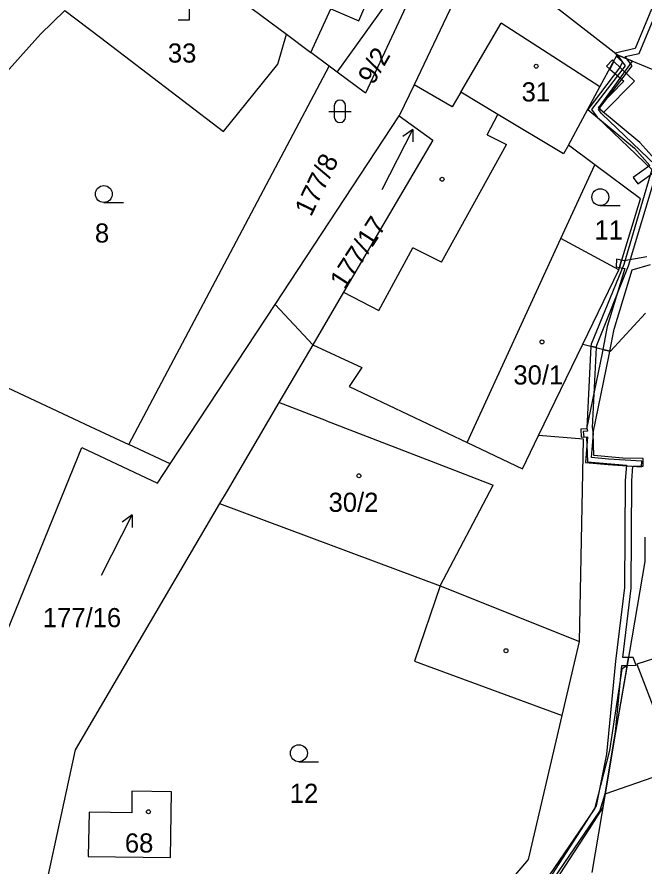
# Model space of a CAD drawing. Extents: x -779723 to -777378, y -1011169 to -1009297.
# Drawn here: x -779222.9 to -779167.2, y -1010377.1 to -1010301.7 of the extents above; entities that cross this region are included whole.
import ezdxf

# ---------------------------------------------------------------- set-up
doc = ezdxf.new("R2010")
doc.units = 0
for name, color, linetype in [('Hranice parcel', 7, 'Continuous'), ('Parcelní čísla', 7, 'Continuous'), ('Vnitřní kresba', 7, 'Continuous'), ('Věcná břemena k části', 7, 'Continuous'), ('Značky budov', 7, 'Continuous'), ('Značky kultur', 7, 'Continuous')]:
    doc.layers.add(name, color=color, linetype=linetype)

msp = doc.modelspace()

# ---------------------------------------------------------------- linework, layer by layer
at = {"layer": 'Hranice parcel'}
for p, q in [((-779198.99, -1010303.26), (-779196.83, -1010304.88)), ((-779195.2, -1010306.1), (-779196.83, -1010304.88)), ((-779212.98, -1010339.7), (-779195.2, -1010306.1)), ((-779194.49, -1010306.63), (-779195.2, -1010306.1)), ((-779187.65, -1010307.74), (-779188.97, -1010310.51)), ((-779200, -1010327.27), (-779188.97, -1010310.51)), ((-779171.61, -1010314.85), (-779173.96, -1010313.1)), ((-779172.68, -1010330.78), (-779169.49, -1010324.18)), ((-779209.31, -1010341.42), (-779200, -1010327.27)), ((-779196.66, -1010330.84), (-779200, -1010327.27)), ((-779176.6, -1010338.9), (-779172.68, -1010330.78)), ((-779209.31, -1010341.42), (-779212.98, -1010339.7)), ((-779170.69, -1010370.7), (-779171.88, -1010377.7))]:
    msp.add_line(p, q, dxfattribs=at)
for points in [[(-779196.83, -1010304.88), (-779195.06, -1010301.02), (-779192.55, -1010302.07), (-779188.41, -1010292.39), (-779193.1, -1010290.28), (-779191.55, -1010286.87)], [(-779194.49, -1010306.63), (-779190.18, -1010300.61), (-779185.64, -1010294.9)], [(-779185.64, -1010294.9), (-779191.98, -1010308.5), (-779194.49, -1010306.63)], [(-779209.36, -1010295.51), (-779204.33, -1010299.27), (-779198.99, -1010303.26)], [(-779181.85, -1010295.53), (-779183.92, -1010299.88), (-779187.65, -1010307.74)], [(-779169.61, -1010305.1), (-779177.81, -1010298.69), (-779179.01, -1010297.75), (-779181.85, -1010295.53)], [(-779241.34, -1010326.4), (-779229.64, -1010317.38), (-779225.92, -1010308.91), (-779220.82, -1010303.25), (-779218.66, -1010301.14)], [(-779218.66, -1010301.14), (-779215.5, -1010303.55), (-779204.57, -1010311.9), (-779199.75, -1010305.93), (-779198.99, -1010303.26)], [(-779173.96, -1010313.1), (-779171.15, -1010307.94), (-779169.61, -1010305.1)], [(-779169.61, -1010305.1), (-779160.99, -1010308.63), (-779155.46, -1010307.78), (-779148.16, -1010306.65)], [(-779173.96, -1010313.1), (-779174.39, -1010313.89), (-779180.21, -1010310.38), (-779183.51, -1010308.4), (-779184.27, -1010309.7), (-779187.65, -1010307.74)], [(-779188.97, -1010310.51), (-779186, -1010312.66), (-779190.73, -1010320.73), (-779193.92, -1010326.17), (-779196.66, -1010330.84)], [(-779169.49, -1010324.18), (-779174.62, -1010321.41), (-779171.61, -1010314.85)], [(-779169.49, -1010324.18), (-779167.55, -1010317.87), (-779171.61, -1010314.85)], [(-779241.34, -1010326.4), (-779216.41, -1010338.1), (-779212.98, -1010339.7)], [(-779172.68, -1010330.78), (-779170.22, -1010331.41), (-779167.12, -1010328.04)], [(-779196.66, -1010330.84), (-779199.66, -1010335.95), (-779204.25, -1010343.79), (-779204.93, -1010344.94)], [(-779196.66, -1010330.84), (-779192.3, -1010332.84), (-779193.43, -1010334.55), (-779182.94, -1010339.51), (-779178.02, -1010341.84), (-779176.6, -1010338.9)], [(-779174.51, -1010363.75), (-779172.96, -1010357.18), (-779172.6, -1010339.21), (-779176.6, -1010338.9)], [(-779237.61, -1010383.13), (-779227.1, -1010364.33), (-779217.17, -1010339.95), (-779210.43, -1010343.11), (-779209.31, -1010341.42)], [(-779204.93, -1010344.94), (-779217.76, -1010366.81), (-779222.02, -1010386.49)], [(-779204.93, -1010344.94), (-779185.33, -1010352.25), (-779187.61, -1010358.93), (-779174.51, -1010363.75)], [(-779167.16, -1010347.93), (-779167.17, -1010350.08), (-779168.77, -1010359.47), (-779169.76, -1010365.24), (-779170.69, -1010370.7)], [(-779170.69, -1010370.7), (-779164.31, -1010368.5), (-779150.92, -1010363.88), (-779148.14, -1010362.87)], [(-779181.94, -1010381.76), (-779177.51, -1010376.54), (-779174.51, -1010363.75)], [(-779212.73, -1010372.38), (-779216.52, -1010372.33), (-779216.59, -1010376.27), (-779209.28, -1010376.35), (-779209.21, -1010370.54), (-779212.71, -1010370.47), (-779212.73, -1010372.38)]]:
    msp.add_lwpolyline(points, dxfattribs=at)
at = {"layer": 'Vnitřní kresba'}
for p, q in [((-779183.51, -1010308.4), (-779179.93, -1010302.29)), ((-779171.15, -1010307.94), (-779179.93, -1010302.29)), ((-779181.18, -1010312.2), (-779180.21, -1010310.38)), ((-779181.18, -1010312.2), (-779179.44, -1010313.05)), ((-779185.22, -1010323.51), (-779179.44, -1010313.05)), ((-779182.94, -1010339.51), (-779174.62, -1010321.41)), ((-779190.79, -1010327.79), (-779187.78, -1010322.22)), ((-779185.22, -1010323.51), (-779187.78, -1010322.22)), ((-779193.92, -1010326.17), (-779190.79, -1010327.79)), ((-779195.44, -1010337.58), (-779199.66, -1010335.95)), ((-779195.44, -1010337.58), (-779184.06, -1010341.97)), ((-779184.06, -1010341.97), (-779180.63, -1010343.29)), ((-779185.33, -1010352.25), (-779180.63, -1010343.29)), ((-779185.33, -1010352.25), (-779172.96, -1010357.18)), ((-779152.93, -1010354.43), (-779167.87, -1010359.19)), ((-779167.87, -1010359.19), (-779166.01, -1010364.05))]:
    msp.add_line(p, q, dxfattribs=at)
at = {"layer": 'Věcná břemena k části'}
for points in [[(-779165.25, -1010299.1), (-779165.69, -1010298.88), (-779168.03, -1010304.53), (-779169.81, -1010304.95), (-779169.61, -1010305.1), (-779168.76, -1010305.45), (-779168.92, -1010305.23), (-779167.67, -1010304.97)], [(-779170.83, -1010310.2), (-779168.09, -1010307.42), (-779169.92, -1010305.67), (-779170.29, -1010306.35), (-779169.03, -1010307.44), (-779171.29, -1010309.74)], [(-779170.29, -1010306.35), (-779169.92, -1010305.67), (-779170.05, -1010305.54), (-779170.57, -1010306.1)], [(-779169.23, -1010323.33), (-779169.69, -1010323.24), (-779169.71, -1010323.91), (-779169.42, -1010323.97)], [(-779171.95, -1010330.97), (-779172.32, -1010338.23), (-779172.27, -1010338.5), (-779172.63, -1010338.54), (-779172.57, -1010339.04), (-779172.25, -1010339), (-779172.45, -1010341.3), (-779170.41, -1010341.47), (-779167.46, -1010341.66), (-779167.43, -1010341.17), (-779170.38, -1010340.98), (-779171.91, -1010340.84), (-779171.72, -1010338.7), (-779171.82, -1010338.19), (-779171.45, -1010331.09)], [(-779168.62, -1010358.6), (-779168.74, -1010359.3), (-779167.95, -1010359.28), (-779168.21, -1010358.59)], [(-779168.84, -1010359.9), (-779168.74, -1010359.3), (-779169.22, -1010359.65), (-779170.31, -1010366.86), (-779171.63, -1010372.03), (-779178.35, -1010381.89), (-779186.23, -1010391.51), (-779188.9, -1010390.68), (-779189.2, -1010391.07), (-779186.47, -1010391.96), (-779189.03, -1010399.39), (-779189.26, -1010403.35), (-779188.7, -1010402.34), (-779188.53, -1010399.49), (-779185.93, -1010391.92), (-779177.95, -1010382.19), (-779171.17, -1010372.23), (-779170.69, -1010370.7)]]:
    msp.add_lwpolyline(points, close=True, dxfattribs=at)
for points in [[(-779166.02, -1010314.64), (-779167.62, -1010312.88), (-779171.28, -1010309.83), (-779168.26, -1010305.65), (-779169.61, -1010305.1), (-779169.67, -1010305.21), (-779169.15, -1010305.75), (-779169.41, -1010306.24), (-779172.24, -1010309.93), (-779168.1, -1010313.38), (-779166.71, -1010314.91), (-779168.2, -1010315.98), (-779167.79, -1010316.55), (-779166.22, -1010315.42)], [(-779166.18, -1010314.93), (-779171.03, -1010310.31), (-779171.29, -1010309.95), (-779168.29, -1010306.08), (-779168.76, -1010305.45), (-779169.61, -1010305.1), (-779168.91, -1010306.08), (-779171.91, -1010309.93), (-779171.41, -1010310.63), (-779166.54, -1010315.27), (-779169.04, -1010323.72), (-779171.94, -1010330.78), (-779171.95, -1010330.97), (-779171.45, -1010331.09), (-779171.44, -1010330.86), (-779168.61, -1010323.84), (-779166.16, -1010315.66)], [(-779166.98, -1010323.02), (-779169.01, -1010323.38), (-779169.23, -1010323.33), (-779169.42, -1010323.97), (-779168.95, -1010324.06), (-779170.52, -1010329.22), (-779170.9, -1010331.24), (-779170.27, -1010331.4), (-779169.89, -1010329.45), (-779168.3, -1010324.18), (-779166.66, -1010323.72)], [(-779175.58, -1010379.18), (-779172.09, -1010373.8), (-779170.9, -1010371.95), (-779170.69, -1010370.7), (-779169.76, -1010365.24), (-779169.2, -1010359.31), (-779168.74, -1010359.3), (-779168.62, -1010358.6), (-779169.12, -1010358.61), (-779168.37, -1010352.44), (-779168.32, -1010342.91), (-779168.22, -1010341.61), (-779167.31, -1010341.62), (-779167.31, -1010340.92), (-779169.12, -1010340.9), (-779171.69, -1010340.67), (-779171.75, -1010338.65), (-779170.33, -1010331.72), (-779170.27, -1010331.4), (-779170.9, -1010331.24), (-779170.97, -1010331.59), (-779172.35, -1010338.31), (-779172.84, -1010338.33), (-779172.82, -1010339.03), (-779172.34, -1010339.01), (-779172.27, -1010341.23), (-779168.81, -1010341.53), (-779168.92, -1010342.89), (-779168.97, -1010352.4), (-779169.77, -1010358.94), (-779170.57, -1010367.18), (-779171.48, -1010371.76), (-779172.59, -1010373.48), (-779176.06, -1010378.84)]]:
    msp.add_lwpolyline(points, dxfattribs=at)
at = {"layer": 'Značky budov'}
for centre in [(-779176.817, -1010306.099), (-779185.167, -1010316.139), (-779176.297, -1010330.579), (-779192.557, -1010342.469), (-779179.497, -1010357.999), (-779211.247, -1010372.299)]:
    msp.add_circle(centre, 0.175, dxfattribs=at)
at = {"layer": 'Značky kultur'}
for p, q in [((-779207.6, -1010301.97), (-779207.6, -1010300.97)), ((-779208.601, -1010301.97), (-779207.6, -1010301.97)), ((-779194.741, -1010309.611), (-779194.741, -1010310.612)), ((-779193.739, -1010310.612), (-779193.739, -1010309.611)), ((-779195.241, -1010310.111), (-779193.239, -1010310.111)), ((-779190.497, -1010317.052), (-779187.773, -1010311.706)), ((-779187.773, -1010311.706), (-779188.663, -1010312.349)), ((-779187.773, -1010311.706), (-779187.769, -1010312.804)), ((-779215.203, -1010318.2), (-779213.453, -1010318.2)), ((-779171.123, -1010318.48), (-779169.373, -1010318.48)), ((-779215.407, -1010351.292), (-779212.683, -1010345.946)), ((-779212.683, -1010345.946), (-779213.573, -1010346.589)), ((-779212.683, -1010345.946), (-779212.679, -1010347.044)), ((-779197.883, -1010367.85), (-779196.133, -1010367.85))]:
    msp.add_line(p, q, dxfattribs=at)
for centre in [(-779215.203, -1010317.45), (-779171.123, -1010317.73), (-779197.883, -1010367.1)]:
    msp.add_circle(centre, 0.75, dxfattribs=at)
for centre, start, end in [((-779194.24, -1010309.611), 0, 180), ((-779194.24, -1010310.611), 180, 359.98789)]:
    msp.add_arc(centre, 0.5, start, end, dxfattribs=at)

# ---------------------------------------------------------------- texts
at = {"layer": 'Parcelní čísla'}
for s, p in [('33', (-779209.52, -1010305.78)), ('31', (-779178.11, -1010309.23)), ('8', (-779216, -1010321.76)), ('11', (-779171.64, -1010321.49)), ('30/1', (-779178.84, -1010334.36)), ('30/2', (-779195.25, -1010345.669)), ('177/16', (-779220.625, -1010355.91)), ('12', (-779198.7, -1010371.51)), ('68', (-779213.34, -1010375.919))]:
    msp.add_text(s, height=1.7, dxfattribs=at).set_placement(p)
for s, rotation, p in [('9/2', 60, (-779191.278, -1010307.834)), ('177/8', 64, (-779196.816, -1010319.532)), ('177/17', 57, (-779193.827, -1010326.005))]:
    msp.add_text(s, height=1.7, rotation=rotation, dxfattribs=at).set_placement(p)

doc.saveas('drawing.dxf')
